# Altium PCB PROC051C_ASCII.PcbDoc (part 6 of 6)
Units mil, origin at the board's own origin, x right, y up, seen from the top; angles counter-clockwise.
Board outline 3304.03 x 2647.77 mil, 6 copper layers (TOP, L2, L3, L4, L5, BOTTOM), stack 55.54 mil thick; 370 components, 273 nets, 1273 pads, 1381 vias.
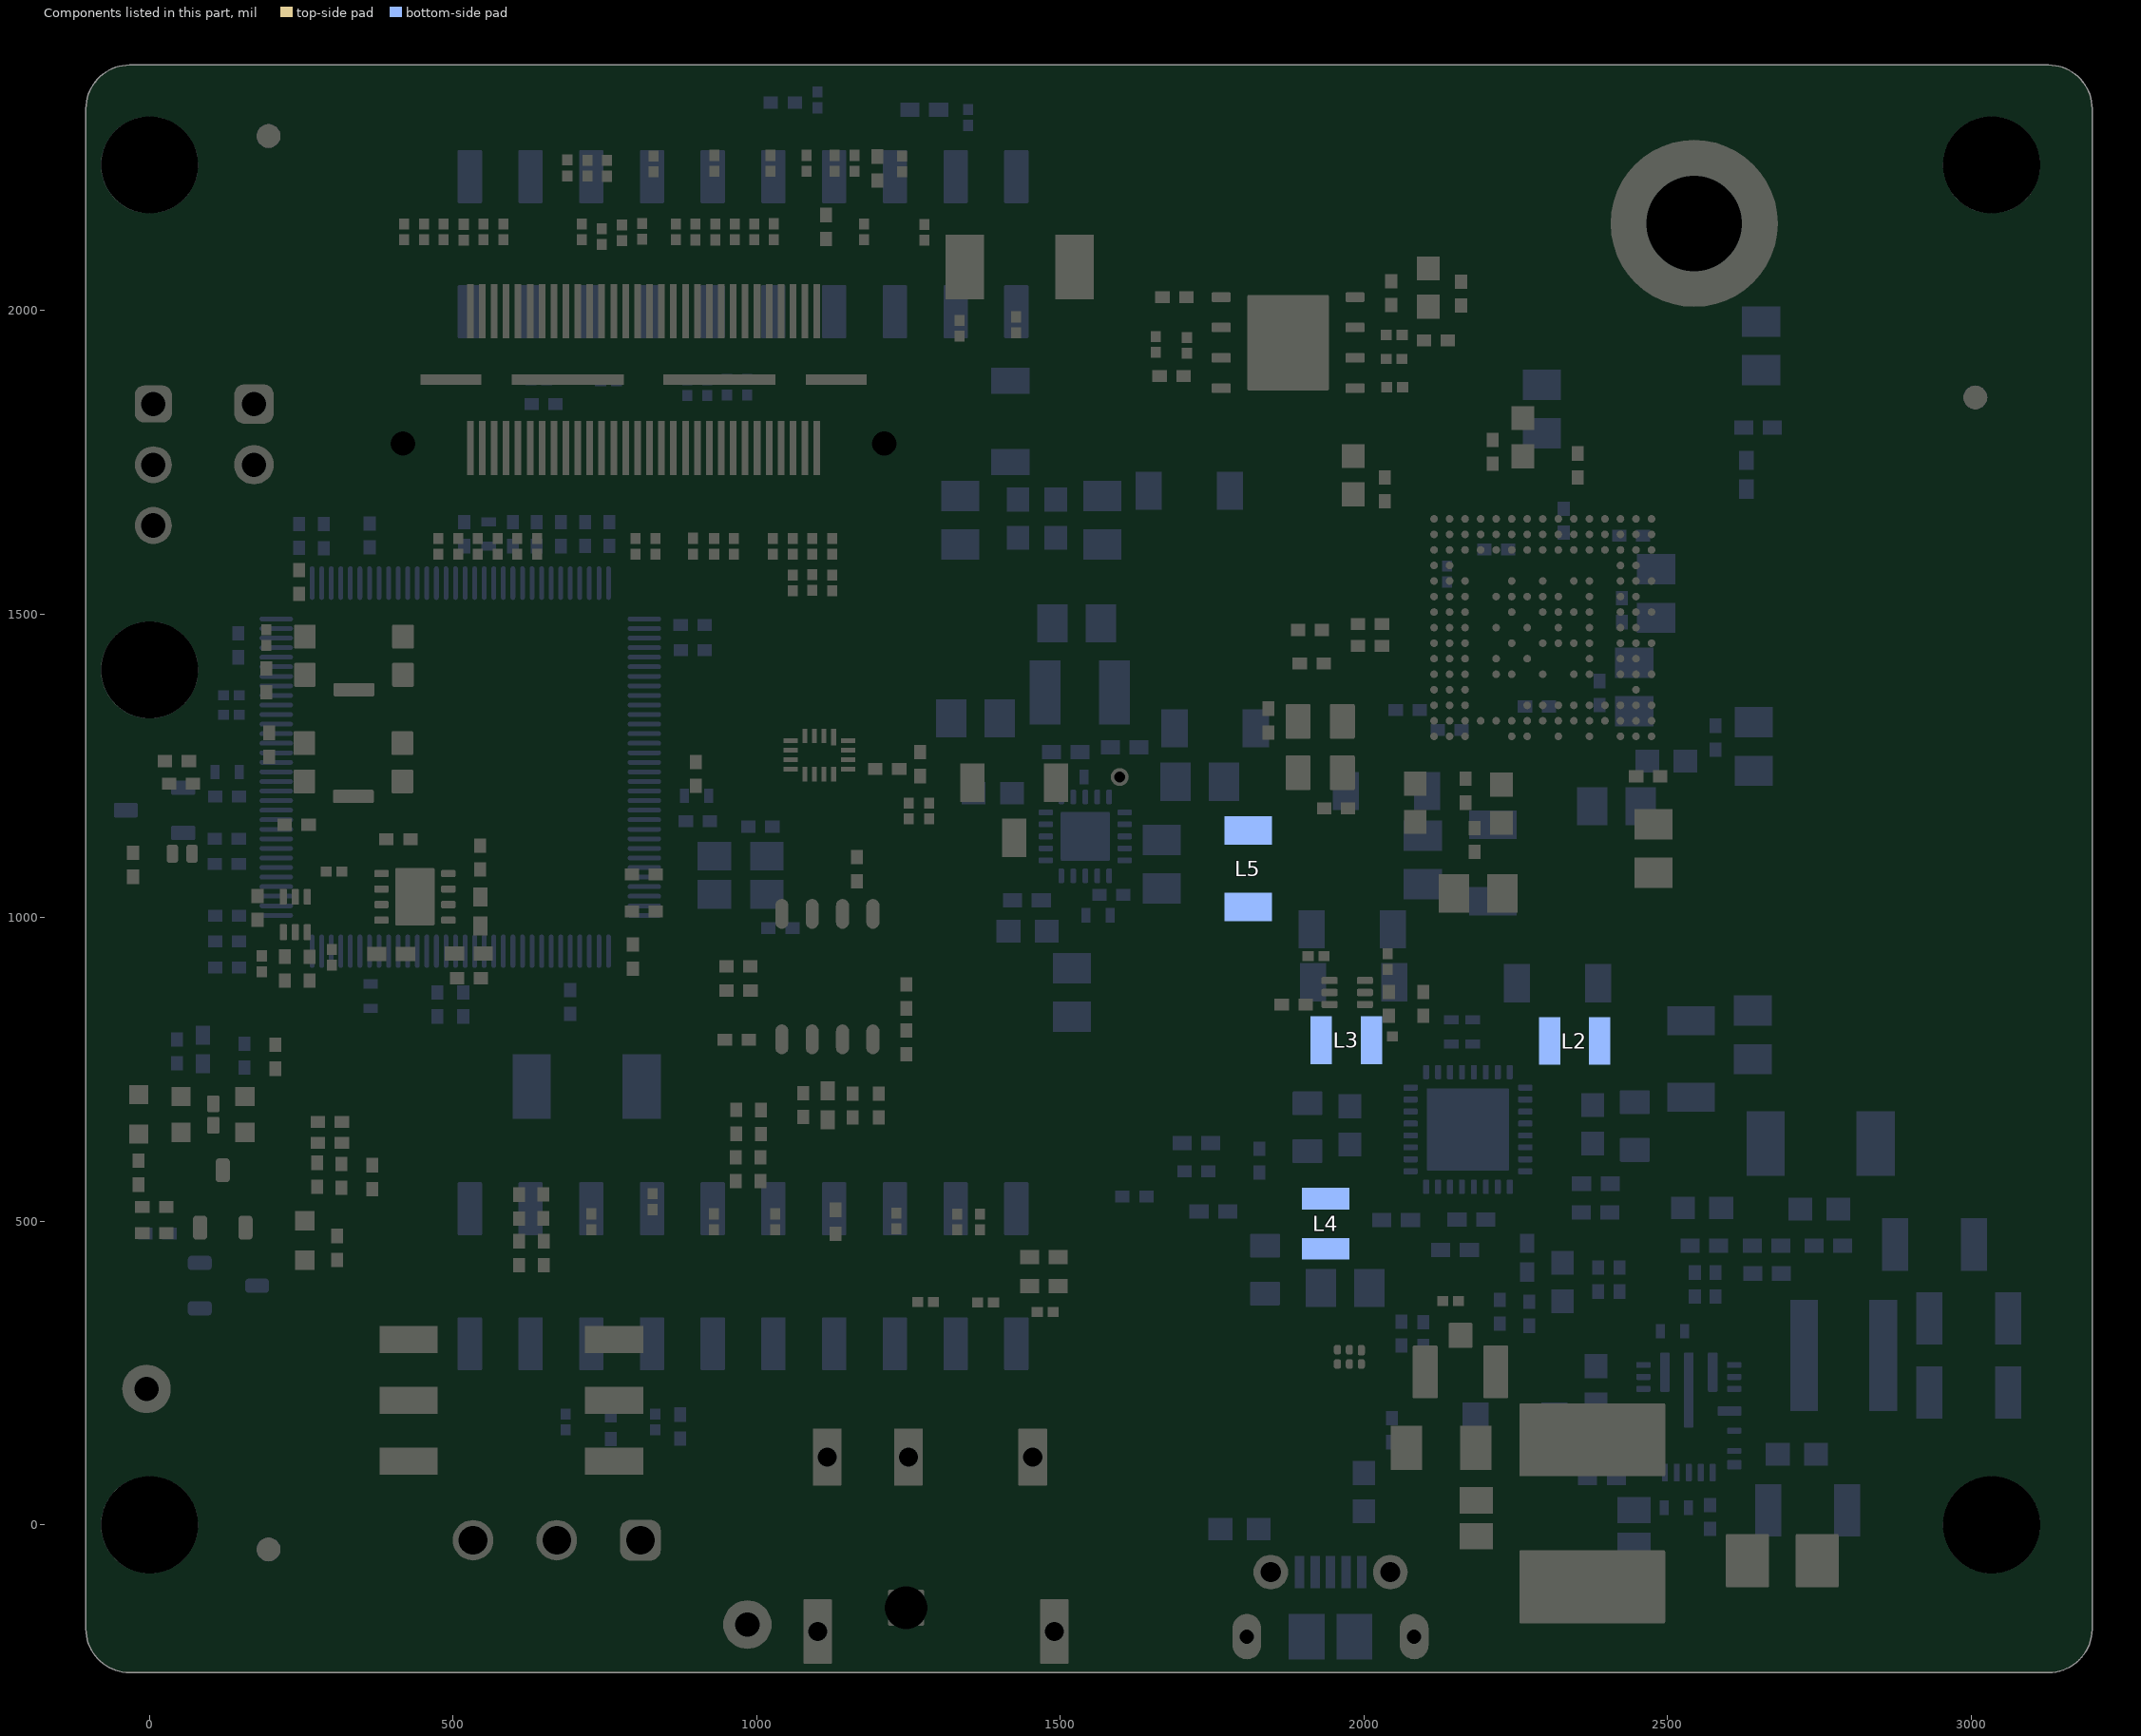
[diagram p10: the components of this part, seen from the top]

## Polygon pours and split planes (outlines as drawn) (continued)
no net on M5 Assembly Top (solid): 3048.2,1870.7 ccw(c3006.2,1870.7) 3006.2,1912.7 ccw(c3006.2,1870.7) 2964.2,1870.7 ccw(c3006.2,1870.7) 3006.2,1828.7 ccw(c3006.2,1870.7) 3048.2,1870.7
no net on M5 Assembly Top (solid): 238,-40.5 ccw(c196,-40.5) 196,1.5 ccw(c196,-40.5) 154,-40.5 ccw(c196,-40.5) 196,-82.5 ccw(c196,-40.5) 238,-40.5
GND on L5 "L5_GND_P1103" (solid, remove dead copper, pour order 1103): 3156.74,-243.26 -87.75,-243.25 -116,-214.99 -116,2367 -75,2408 3157,2408 3199.26,2365.74 3199.26,-200.74

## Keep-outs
TOP:
  circle w10: c3033.56,2240 r92.09
  circle w10: c3033.56,0 r92.09
L2:
  circle w10: c1209.9,1781.14 r44.95
  circle w10: c417.38,1781.14 r44.95
  circle w10: c3033.56,0 r92.09
  circle w10: c3033.56,2240 r92.09
L3:
  circle w10: c3033.56,2240 r92.09
  circle w10: c3033.56,0 r92.09
L4:
  circle w10: c1209.9,1781.14 r44.95
  circle w10: c3033.56,0 r92.09
  circle w10: c3033.56,2240 r92.09
L5:
  circle w10: c1209.9,1781.14 r44.95
  circle w10: c417.38,1781.14 r44.95
  circle w10: c3033.56,2240 r92.09
  circle w10: c3033.56,0 r92.09
BOTTOM:
  circle w10: c3033.56,2240 r92.09
  circle w10: c3033.56,0 r92.09
Keep-Out Layer:
  lines w4: -102.75,-171.24 ccw(c-32.75,-171.24) -32.75,-241.24 3127.25,-241.24 ccw(c3127.25,-171.24) 3197.25,-171.24 3197.25,2332.5 ccw(c3127.25,2332.5) 3127.25,2402.5 -32.75,2402.5 ccw(c-32.75,2332.5) -102.75,2332.5 -102.75,-171.24
  text ".Layer_Name" at 269,-1200.49 h60

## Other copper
TOP:
  text ".Layer_Name" at 269,-1200.49 h60
L2:
  text ".Layer_Name" at 265.96,-1198.29 h60
L3:
  text ".Layer_Name" at 266.3,-1199.15 h60
L4:
  text ".Layer_Name" at 270.35,-1203.19 h60
L5:
  text ".Layer_Name" at 265.96,-1201.5 h60
BOTTOM:
  text ".Layer_Name" at 269,-1200.49 h60

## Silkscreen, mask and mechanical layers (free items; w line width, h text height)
Top Overlay:
  lines w6: 1944.01,252.57 1944.01,304.68 2000.32,304.68 2008.7,296.3 2008.7,252.57 1944.01,252.57
  lines w10: 56,1744 73.53,1726.47 90.78,1709.22 90.78,1631.82 84.96,1637.64 97.42,1637.64 91.6,1631.82 ; 117,629 118,629 133,614 145,614 ; 259.69,1058.63 ccw(c266.87,1055.3) 259.69,1058.63 ; 359.73,1070.26 ccw(c366.91,1066.94) 359.73,1070.26 ; 827.2,103.68 ccw(c834.38,100.36) 827.2,103.68 ; 1098.62,2058.28 ccw(c1105.8,2054.96) 1098.62,2058.28 ; 1126.81,1323.46 ccw(c1133.99,1320.13) 1126.81,1323.46 ; 1191.31,1043.36 ccw(c1198.49,1040.04) 1191.31,1043.36 ; 1731,2042.5 ccw(c1738.18,2039.17) 1731,2042.5
  lines w25: 1280,1667.5 1280,2079.5 ; 1683.5,655.5 1986,655.5
  lines w30: 1276,742 1276,655.5 1357.1,655.5 ; 1276,932 1276,1112 ; 1598,2095.5 2044,2095.5 ; 2166,2095.5 2372,2095.5 ; 2668,1805.5 2668,2019.5
  text "1" at 1168,2055 h30 r90
  text "59" at 471,2041 h30 r90
  text "HD_CONN" at 302,1910 h30 r90
  text "VPP_1P7" at 278,1714 h30 r90
  text "2" at 1167,1706 h30 r90
  text "60" at 476,1681 h30 r90
  text "GND" at 106,1531 h30 r90
  text "1843-EVM" at 1345,1523 h30
  text "PROC051" at 1291,1458 h30
  text "REV C" at 1502,1456 h30
  text "GPIO1" at 548,1388 h30 r90
  text "SPI" at 1510,1277 h30 r90
  text "CAN" at 1368,1275 h30 r90
  text "NRST" at 548,1203 h30 r90
  text "GPIO_2" at -2,755.84 h30 r90
  text "WRM_RST" at 66,751 h30 r90
  text "NERR" at 171,749 h30 r90
  text "PWR" at 121,748 h30 r90
  text "NRST" at 256.76,548 h30 r90
  text "ON" at 509,403 h30 r90
  text "OFF" at 709,402 h30 r90
  text "SOP0" at 243,290 h30
  text "SOP1" at 249,190 h30
  text "5V_IN" at 1130,173 h30 r90
  text "SOP2" at 242,93 h30
  text "USB" at 1958,-107 h30 r90
  text "GND" at 702,-148 h30 r90
  text "CAN_L" at 541,-209 h30 r90
  text "CAN_H" at 819,-209 h30 r90
  text ".Layer_Name" at 269,-1200.49 h60
Bottom Overlay:
  drawing of 5487 lines, arcs and shapes, not listed
  text "GND" at 545,2389 h35 r90
  text "20" at 1517,2269 h30 r90
  text "2" at 465,2248 h30 r90
  text "19" at 1522,2037 h30 r90
  text "1" at 466,1986 h30 r90
  text "P1" at 14,1946 h30 r90
  text "P7" at 262,1899 h30 r90
  text "WD_ENABLE" at 1778,670 h30
  text "GND" at 640,644 h25 r90
  text "20" at 1522,552 h30 r90
  text "2" at 454,502 h30 r90
  text "WD_DISABLE" at 1793,448 h30
  text "1" at 457,339 h30 r90
  text "19" at 1520,330 h30 r90
  text "GND" at 654,207 h30 r90
  text "5V_IN" at 1551,194 h30 r90
  text "CAN_H" at 931,98 h30 r90
  text "CAN_L" at 439,94 h30 r90
  text ".Layer_Name" at 269,-1200.49 h60
Top Paste:
  text ".Layer_Name" at 269,-1200.49 h60
Bottom Paste:
  text ".Layer_Name" at 269,-1200.49 h60
Top Solder:
  text ".Layer_Name" at 269,-1200.49 h60
  text ".Layer_Name" at 269,-1200.49 h60
Bottom Solder:
  text ".Layer_Name" at 269,-1200.49 h60
Drill Guide:
  text ".Layer_Name" at 269,-1200.49 h60
M1 Board Outline:
  lines w4: -102.75,-171.24 ccw(c-32.75,-171.24) -32.75,-241.24 3127.25,-241.24 ccw(c3127.25,-171.24) 3197.25,-171.24 ; -102.75,-171 -102.75,2331.5 ; -102.75,2332.5 cw(c-32.75,2332.5) -32.75,2402.5 3127.25,2402.5 cw(c3127.25,2332.5) 3197.25,2332.5 3197.25,-172
  text ".Layer_Name" at 270.78,-1200.89 h60
M2 Board Dimensions:
  rectangle: -183,-742 192,-617
  rectangle: -308,-617 -183,-492
  lines w7: -308,-617 692,-617 ; -183,-742 -183,-492 ; -58,-742 -58,-492 ; 192,-742 192,-492 ; 442,-742 442,-492 ; -308,-742 -308,-492 692,-492 692,-742 -308,-742
  text ".Layer_Name" at 268.79,-1200.89 h60
M3 3D STEP Top:
  text ".Layer_Name" at 269,-1200.49 h60
M4 3D STEP Bottom:
  lines w6: 711,2169 705,2169 ; 1282,2245 1333,2245 1374,2204 1731,2204 1763,2236 1763,2317 1709,2371 1327,2371 1282,2326 1282,2227 1246,2191 1062,2191 1048,2177 1048,2169 ; 705,2169 1048,2169 ; 705,2169 693,2157 693,2093 703,2083 1043,2083 1054,2094 1054,2163 1048,2169
  text ".Layer_Name" at 269,-1200.49 h60
M5 Assembly Top:
  lines w10: -600,-1272.17 6000,-1272.17 ; -600,-1068.83 6002,-1068.83 ; -600,-865.5 -600,-1475.5 3405,-1475.5 6002,-1475.5 6002,-865.5 -599.5,-865.5 -599.5,-1475.5 976,-1475.5 ; 1865,-1475.5 1865,-865.5 ; 3132,-1068.83 3132,-865.5 ; 3972,-1068.83 3972,-865.5 ; 4594,-1482 4594,-1279.17
  text "COMPONENTS MARKED 'DNP' SHOULD NOT BE POPULATED." at 845.5,-660.5 h60
  text "ASSEMBLY VARIANT:" at 845,-776 h60
  text ".VariantName" at 1881,-776 h60
  text "PCB VIEWED FROM TOP SIDE" at -536.5,-997.67 h60
  text "BOARD #:" at 1940,-997.67 h60
  text ".PRJ_Number" at 2485.5,-997.67 h60
  text "REV:" at 3330,-997.67 h60
  text ".PCB_Rev" at 3621.5,-997.67 h60
  text "SVN REV:" at 4168,-997.67 h60
  text ".VersionControl_RevNumber" at 4674,-997.67 h60
  text ".Layer_Name" at 269,-1200.49 h60
  text "TID #:" at 1940,-1201 h60
  text ".TID" at 2485.5,-1201 h60
  text "LAYER NAME =" at -525.56,-1204.81 h60
  text "PLOT NAME =" at -536.5,-1406.34 h60
  text ".plot_File_Name" at 269,-1406.34 h60
  text "GENERATED    :" at 1942,-1406.34 h60
  text ".Print_Date" at 2811.5,-1406.34 h60
  text ".Print_Time" at 3540.5,-1406.34 h60
  text "TEXAS INSTRUMENTS" at 4805,-1406.34 h60
M6 Assembly Bottom:
  lines w10: -600.5,-1069.33 6001.5,-1069.33 ; -598.5,-1272.67 6001.5,-1272.67 ; 807.5,-1482.5 807.5,-1279.67 ; 1429.5,-1069.33 1429.5,-866 ; 2269.5,-1069.33 2269.5,-866 ; 3536.5,-1476 3536.5,-866 ; 4425.5,-1476 6001,-1476 6001,-866 -600.5,-866 -600.5,-1476 1996.5,-1476 6001.5,-1476 6001.5,-866
  text "COMPONENTS MARKED 'DNP' SHOULD NOT BE POPULATED." at 5794,-660 h60
  text ".VariantName" at 4750,-776 h60
  text "ASSEMBLY VARIANT:" at 5789,-776 h60
  text ".VersionControl_RevNumber" at 727.5,-998.17 h60
  text "SVN REV:" at 1233.5,-998.17 h60
  text ".PCB_Rev" at 1780,-998.17 h60
  text "REV:" at 2071.5,-998.17 h60
  text ".PRJ_Number" at 2916,-998.17 h60
  text "BOARD #:" at 3461.5,-998.17 h60
  text "PCB VIEWED FROM BOTTOM SIDE" at 5938,-998.17 h60
  text ".TID" at 2916,-1201.5 h60
  text "TID #:" at 3461.5,-1201.5 h60
  text "LAYER NAME =" at 5938.09,-1203.59 h60
  text ".Layer_Name" at 5191.24,-1206.1 h60
  text "TEXAS INSTRUMENTS" at 596.5,-1406.84 h60
  text ".Print_Time" at 1861,-1406.84 h60
  text ".Print_Date" at 2590,-1406.84 h60
  text "GENERATED    :" at 3459.5,-1406.84 h60
  text ".plot_File_Name" at 5132.5,-1406.84 h60
  text "PLOT NAME =" at 5938,-1406.84 h60
M9 Title Sheet:
  lines w10: -799.5,699.5 -599.5,699.5 ; -799.5,3074.5 -599.5,3074.5 ; -799.5,5449.5 -599.5,5449.5 ; 1700.5,-1675.5 1700.5,-1475.5 ; 1700.5,7624.5 1700.5,7824.5 ; 4200.5,-1675.5 4200.5,-1475.5 ; 4200.5,7624.5 4200.5,7824.5 ; 6013,-1475.5 6013,-865.5 10995.5,-865.5 ; 6700.5,-1675.5 6700.5,-1475.5 ; 6700.5,7624.5 6700.5,7824.5 ; 9200.5,-1675.5 9200.5,-1475.5 ; 9200.5,7624.5 9200.5,7824.5 ; 10995.5,-1475.5 10995.5,-865.5 ; 10995.5,-1165.5 13995.5,-1165.5 ; 10995.5,-565.5 13995.5,-565.5 ; 10996.5,28.5 13996.5,28.5 ; 11700.5,-1675.5 11700.5,-1475.5 ; 11700.5,7624.5 11700.5,7824.5 ; 12500.5,-1465.5 12500.5,-865.5 ; 13995.5,-865.5 10995.5,-865.5 ; 13995.5,-265.5 10995.5,-265.5 ; 14000.5,-275.5 14000.5,-1475.5 ; 14000.5,529 10996.5,529 10995.5,529 10995.5,28.5 10995.5,-265.5 ; 14000.5,699.5 14200.5,699.5 ; 14000.5,3074.5 14200.5,3074.5 ; 14000.5,5449.5 14200.5,5449.5 ; 10995.5,-865.5 10995.5,-265.5 ; 14000.5,-1475.5 -599.5,-1475.5 -599.5,7624.5 14000.5,7624.5 14000.5,-1475.5 ; -799.5,-1675.5 14200.5,-1675.5 14200.5,7824.5 -799.5,7824.5 -799.5,-1675.5
  text "1" at 431.84,7694.5 h70
  text "2" at 2927.5,7694.5 h70
  text "3" at 5416.84,7694.5 h70
  text "4" at 7923.51,7694.5 h70
  text "5" at 10422.5,7694.5 h70
  text "6" at 12927.5,7694.5 h70
  text "A" at -724.5,6551.5 h70
  text "A" at 14075.5,6551.5 h70
  text "B" at -724.5,4171.5 h70
  text "B" at 14075.5,4171.5 h70
  text "C" at -724.5,1796.5 h70
  text "C" at 14075.5,1796.5 h70
  text "PROJECT TITLE:" at 11035.5,-64.5 h45
  text ".PRJ_Title" at 11085.5,-197.83 h70
  text "DESIGNED FOR:" at 11035.5,-365.5 h45
  text ".PRJ_Customer" at 11085.5,-505.5 h70
  text "D" at -724.5,-573.5 h70
  text "D" at 14075.5,-573.5 h70
  text "FILE NAME:" at 11035.5,-665.5 h45
  text ".PCB_File_Name_No_Path" at 11085.5,-785.5 h70
  text "Texas Instruments (TI) and/or its licensors do not warrant the accuracy or completeness of this specification" at 6066,-947.34 h45
  text "ENGINEER:" at 11035.5,-955.5 h45
  text "LAYOUT BY:" at 12540.5,-955.5 h45
  text "or any information contained therein. TI and/or its licensors do not warrant that this design will meet" at 6021.01,-1060 h45
  text ".PRJ_Engineer" at 11085.5,-1110.49 h70
  text ".PCB_Layout" at 12591,-1110.49 h70
  text "the specifications, will be suitable for your application or fit for any particular purpose, or will operate in" at 6021.01,-1172.67 h45
  text ".Layer_Name" at 270,-1201.17 h60
  text "ALTIUM DESIGNER VERSION:" at 12540.5,-1265.5 h45
  text "an implementation. TI and/or its licensors do not warrant that the design is production worthy. You should" at 6021.01,-1285.33 h45
  text "completely validate and test your design implementation to confirm the system functionality for your application." at 6066,-1398 h45
  text ".print_Scale" at 11085.5,-1398.83 h70
  text ".Application_BuildNumber" at 12591,-1398.83 h70
  text "1" at 431.84,-1605.5 h70
  text "2" at 2927.5,-1605.5 h70
  text "3" at 5416.84,-1605.5 h70
  text "4" at 7923.51,-1605.5 h70
  text "5" at 10422.5,-1605.5 h70
  text "6" at 12927.5,-1605.5 h70
M10 Fab Notes:
  drawing of 189 lines, arcs and shapes, not listed
  text "DESIGN INFORMATION" at 12074.02,6014.17 h60
  text "MIN. TRACK WIDTH:" at 11429.46,5882.05 h60
  text "MIL" at 12680.46,5882.05 h60
  text "4" at 12497.65,5875.46 h60
  text "MIN. CLEARANCE:" at 11429.46,5757.92 h60
  text "MIL" at 12680.46,5757.92 h60
  text "3" at 12500.45,5756.91 h60
  text "MIN. VIA PAD SIZE:" at 11429.46,5633.8 h60
  text "12.6" at 12418.45,5630.91 h60
  text "MIL" at 12711.42,5628.39 h60
  text "0.05mm (2MIL)" at 12124.46,5503.9 h60
  text "MINIMUM ANNULAR RING" at 11100.23,5495.67 h60
  text "EXTERNAL" at 12832.46,5495.67 h60
  text "PER" at 11300.23,5385.55 h60
  text "IPC-D-275 CLASS 2 LEVEL C" at 11520.23,5385.54 h60
  text "MIL, HOLES" at 13008.46,5285.07 h60
  text "+/-" at 12616,5276.48 h60
  text "+/-" at 13470,5276.48 h60
  text "REGISTRATION TOLERANCES:" at 11100.23,5275.42 h60
  text "METAL" at 12300,5275.42 h60
  text "2" at 12876.2,5275.42 h60
  text "3" at 13709.2,5275.42 h60
  text "MIL" at 13825.46,5275.42 h60
  text "HOLE SIZE TOLERANCE (UNLESS OTHERWISE SPECIFIED):" at 11100.23,5177.1 h60
  text "+/-" at 13470,5174.23 h60
  text "3" at 13709.2,5173.17 h60
  text "MIL" at 13825.46,5173.17 h60
  text "MATERIAL:" at 11025.46,5035.52 h60
  text "FR-4 High Tg" at 12011.9,4907 h60
  text "X" at 12756.42,4898.55 h60
  text "FR-408" at 11446.46,4894.49 h60
  text "OTHER" at 12934.46,4894.49 h60
  text "REFER STACKUP" at 13277.53,4884.65 h60
  text "56.214 MIL(1.42mm) +/-10%" at 11766.56,4751.46 h55
  text "X" at 12936.04,4749.1 h60
  text "57.14 MIL +/-10%" at 13329.52,4748.23 h50
  text "THICKNESS:" at 11100.23,4743.24 h60
  text "OTHER" at 13051.46,4743.24 h60
  text "TOLERANCE:" at 11100.23,4604.92 h60
  text "X" at 11948.46,4604.92 h60
  text "ANSI IPC-6012 TYPE 3 CLASS 2" at 12126.48,4604.92 h60
  text "OTHER +/-" at 12126.46,4460.73 h60
  text "BOW & TWIST:" at 11100.23,4315.54 h60
  text "X" at 11948.46,4315.54 h60
  text "ANSI IPC-6012 TYPE 3 CLASS 2" at 12126.48,4315.54 h60
  text "OTHER +/-" at 12126.46,4168.85 h60
  text "DRILLING:" at 11025.46,4038.23 h60
  text "NC_DRILL FILES" at 12786.46,3933.04 h60
  text "REFERENCE:" at 11100.23,3929.1 h60
  text "X" at 11757.46,3929.01 h60
  text "AS SHOWN" at 11935.46,3929.1 h60
  text "X" at 12658.46,3929.1 h60
  text "OTHER" at 13084.46,3786.85 h60
  text "PTH COPPER THICKNESS:" at 11099.91,3783.32 h60
  text "X" at 12239.14,3783.32 h60
  text "20-30 um" at 12367.14,3783.32 h60
  text "BOARD FINISH:" at 11025.46,3635.73 h60
  text "SILKSCREEN:" at 11180.68,3525.6 h60
  text "X" at 12138.46,3525.6 h60
  text "TOP" at 12255.46,3525.6 h60
  text "X" at 12648.46,3525.6 h60
  text "BOTTOM" at 12766.46,3525.6 h60
  text "SILKSCREEN COLOR:" at 11180.68,3370.41 h60
  text "X" at 12137.46,3370.41 h60
  text "WHITE" at 12255.46,3370.41 h60
  text "OTHER" at 12766.46,3370.41 h60
  text "X" at 12850.6,3228.22 h60
  text "GREEN" at 12386.46,3226.96 h60
  text "OTHER" at 13004.46,3226.96 h60
  text "RED" at 13528.15,3225.88 h60
  text "SOLDER RESIST COLOR:" at 11180.68,3220.1 h60
  text "X" at 12268.46,3072.71 h60
  text "MATTE" at 12386.46,3072.71 h60
  text "SEMI-GLOSS" at 13004,3072.07 h60
  text "IMMERSION GOLD (ENIG)" at 12086.46,2899.94 h60
  text "ENEPIG" at 13424,2892.72 h60
  text "SURFACE FINISH:" at 11025.46,2891.72 h60
  text "IMMERSION SILVER" at 13125.67,2754.86 h60
  text "IMM. TIN/SILVER OR EQUIV" at 11355,2754.4 h60
  text "OTHER" at 12786.46,2750.47 h60
  text "X" at 12603.67,2746.86 h60
  text "NOTES: UNLESS OTHERWISE SPECIFIED." at 4751.98,2687.86 h60
  text "ARRAY/PANEL:" at 11025.46,2595.09 h60
  text "X" at 11906.1,2586.66 h60
  text "CUT AND TRIM PER M1 BOARD OUTLINE" at 12086.46,2586.87 h60
  text "N.C. ROUTE" at 12086.46,2450.9 h60
  text "V. SCORE" at 12952.46,2450.9 h60
  text "1. FOR BOARD THICKNESS AND IMPEDANCE DETAILS REFER STACKUP DOCUMENT." at 4751.98,2425.86 h60
  text "CERTIFICATION:" at 11025.46,2321.77 h60
  text "MATERIALS AND WORKMANSHIP FOR ALL PCBS" at 11750.46,2321.77 h60
  text "2. ALL VIAS ON PAD INCLUDING BGA AREA SHOULD BE FILLED WITH NON CONDUCTIVE EPOXY AND SURFACE SHOULD BE FLAT" at 4741.5,2320.42 h60
  text "TO MEET OR EXCEED THE REQUIREMENTS OF:" at 11750.46,2227.71 h60
  text "THERE ARE MANY VIAS ON THE PCB WHICH ARE EITHER ON THE PADS OR CLOSE TO PADS" at 4860.28,2213.13 h60
  text "THESE NEED TO BE FILLED WITH A NON-CONDUCTIVE EPOXY TO ENSURE FLAT SURFACE." at 4860.28,2112.39 h60
  text "X" at 11387.97,2099.08 h60
  text "ANSI IPC-A-600F CLASS ->" at 11515.96,2099.08 h60
  text "X" at 13163.97,2099.08 h60
  text "2" at 13273.96,2099.08 h60
  text "1" at 12958.96,2097.58 h60
  text "3" at 13627.96,2097.58 h60
  text "BGA AREA VIAS SHOULD BE CAPPED WITH COPPER PLATING TO ENSURE FLAT SURFACE" at 4865.78,2010.86 h60
  text "RoHS" at 12327.96,1951.39 h60
  text "OTHER" at 12972.36,1951.39 h60
  text "PER ORDER" at 13369.42,1951.39 h60
  text "FLATNESS TOLERANCE FOR VIA ON PADS: +0.000 /- 0.001 INCHES ON BOTH SIDES." at 4865.78,1902.77 h60
  text "ALL BOARDS MUST MEET OR EXCEED UL94-V0 REQUIREMENTS." at 11053,1797.57 h60
  text "3. SOLDER MASK OPENING IS KEPT SAME SIZE AS PAD (1:1)" at 4739.9,1789.33 h60
  text "THE MANUFACTURER IS REQUESTED TO RESIZE IT AS PER THEIR SOLDERMASK TOLERANCE EXCEPT NPTH DRILL AND FIDUCIALS." at 4904.94,1687.68 h60
  text "PCB MUST BEAR THE UL94V-0 UL REGISTERED MATERIAL ID NUMBER" at 11053,1681.5 h60
  text "4. VENDOR SHOULD FOLLOW ROHS COMPLIANT PROCESS AND Pb FREE FOR MANUFACTURING" at 4747.64,1564.84 h60
  text "ADDITIONAL REQUIREMENTS:" at 11025.46,1512.08 h60
  text "5. MANUFACTURER'S IDENTIFICATION,DATECODE LETTER SHALL BE SILKSCREENED ON SOLDER SIDE" at 4748.29,1437.55 h60
  text "MICROSECTION:" at 11100.23,1404.95 h60
  text "YES" at 12005.96,1404.95 h60
  text "OF THE BOARD." at 4918.29,1324.55 h60
  text "REQUIRED" at 12867.46,1260.62 h60
  text "BARE BOARD ELEC. TEST:" at 11100.23,1257.76 h60
  text "NONE" at 12405.96,1257.76 h60
  text "X" at 12749.46,1257.76 h60
  text "PER ORDER" at 13459.46,1257.76 h60
  text "6. TRACE WIDTH SHOULD BE ACCURATELY ETCHED. MAX TOLERANCE +/- 1 MIL" at 4748.29,1210.55 h60
  text "7. BOARD DIMENSIONS ARE IN (INCHES)." at 4748.29,1071.55 h60
  text "XX MIL VIAS REQUIRE NON-CONDUCTIVE FILL AND PLANARIZE" at 11268.38,1052.82 h59
  text "XX MIL VIAS REQUIRE CONDUCTIVE FILL AND PLANARIZE" at 11276.38,948.84 h60
  text "8. BOW AND TWIST SHALL NOT EXCEED 0.7% OF LONGEST SIDE" at 4748.29,929.55 h60
  text "9. LAYER TO LAYER REGISTRATION SHALL BE WITHIN +/-2 MIL" at 4748.98,813.84 h60
  text "OUTER XX MIL TRACES REQUIRE 50 OHM SINGLE-ENDED IMPEDANCE" at 11275.39,785.46 h55
  text "10. FOR ANTENNA ETCHING TOLERANCE REFER \"ANTENNA ETCHING REQUIREMENTS\" DOCUMENT." at 4705.37,694.61 h60
  text "LAYER 2 & 3 (INNER LAYERS) XX MIL WIDE, XX MIL SPACE / TRACES REQUIRE 100 OHM DIFFERENTIAL IMPEDANCE" at 11267.39,549.74 h60
  text ".Layer_Name" at 270.6,-1200.89 h60
M11 Gerber Information:
  lines w10: -600,-1272.17 6000,-1272.17 ; -600,-1068.83 6002,-1068.83 ; -600,-865.5 -600,-1475.5 3405,-1475.5 6002,-1475.5 6002,-865.5 -599.5,-865.5 -599.5,-1475.5 976,-1475.5 ; 1865,-1475.5 1865,-865.5 ; 3132,-1068.83 3132,-865.5 ; 3972,-1068.83 3972,-865.5 ; 4594,-1482 4594,-1279.17
  text "ALL ARTWORK VIEWED FROM TOP SIDE" at -536.5,-997.67 h60
  text "BOARD #:" at 1940,-997.67 h60
  text ".PRJ_Number" at 2485.5,-997.67 h60
  text "REV:" at 3330,-997.67 h60
  text ".PCB_Rev" at 3621.5,-997.67 h60
  text "SVN REV:" at 4168,-997.67 h60
  text ".VersionControl_RevNumber" at 4674,-997.67 h60
  text "LAYER NAME =" at -536.5,-1200.49 h60
  text "TID #:" at 1940,-1201 h60
  text ".TID" at 2485.5,-1201 h60
  text "PLOT NAME =" at -536.5,-1406.34 h60
  text ".plot_File_Name" at 269,-1406.34 h60
  text "GENERATED    :" at 1942,-1406.34 h60
  text ".Print_Date" at 2811.5,-1406.34 h60
  text ".Print_Time" at 3540.5,-1406.34 h60
  text "TEXAS INSTRUMENTS" at 4805,-1406.34 h60
M12 Stackup:
  drawing of 417 lines, arcs and shapes, not listed
  text "LAYER STACKUP :" at 5183.41,7377.07 h60
  text "Layer" at 5204.39,7196.49 h60
  text "Name" at 5614.31,7196.49 h60
  text "Material" at 6544.05,7196.49 h60
  text "Thickness" at 7733.71,7196.49 h60
  text "Constant" at 8383.55,7196.49 h60
  text "Board Layer Stack" at 8953.41,7196.49 h60
  text "1" at 5204.39,7076.49 h60
  text "Top Overlay" at 5614.31,7076.49 h60
  text "2" at 5204.39,6956.49 h60
  text "Top Solder" at 5614.31,6956.49 h60
  text "Solder Resist" at 6544.05,6956.49 h60
  text "0.80mil" at 7733.71,6956.49 h60
  text "3.5" at 8383.55,6956.49 h60
  text "3" at 5204.39,6836.49 h60
  text "TOP" at 5614.31,6836.49 h60
  text "Copper" at 6544.05,6836.49 h60
  text "1.60mil" at 7733.71,6836.49 h60
  text "4" at 5204.39,6716.49 h60
  text "Dielectric1" at 5614.31,6716.49 h60
  text "Rogers 4835" at 6544.05,6716.49 h60
  text "4.00mil" at 7733.71,6716.49 h60
  text "3.66" at 8383.55,6716.49 h60
  text "L1-L2" at 4858.49,6644.53 h60 r90
  text "5" at 5204.39,6596.49 h60
  text "L2" at 5614.31,6596.49 h60
  text "Copper" at 6544.05,6596.49 h60
  text "1.20mil" at 7733.71,6596.49 h60
  text "6" at 5204.39,6476.49 h60
  text "Dielectric2" at 5614.31,6476.49 h60
  text "370HR Prepreg 1080" at 6544.05,6476.49 h60
  text "5.70mil" at 7733.71,6476.49 h60
  text "3.9" at 8383.55,6476.49 h60
  text "7" at 5204.39,6356.49 h60
  text "L3" at 5614.31,6356.49 h60
  text "Copper" at 6544.05,6356.49 h60
  text "1.20mil" at 7733.71,6356.49 h60
  text "8" at 5204.39,6236.49 h60
  text "Dielectric3" at 5614.31,6236.49 h60
  text "370HR Prepreg 1080" at 6544.05,6236.49 h60
  text "28.00mil" at 7733.71,6236.49 h60
  text "4.36" at 8383.55,6236.49 h60
  text "L1-L6" at 4676.89,6155.29 h60 r90
  text "9" at 5204.39,6116.49 h60
  text "L4" at 5614.31,6116.49 h60
  text "Copper" at 6544.05,6116.49 h60
  text "1.20mil" at 7733.71,6116.49 h60
  text "10" at 5204.39,5996.49 h60
  text "Dielectric4" at 5614.31,5996.49 h60
  text "370HR Prepreg 1080" at 6544.05,5996.49 h60
  text "5.84mil" at 7733.71,5996.49 h60
  text "3.9" at 8383.55,5996.49 h60
  text "11" at 5204.39,5876.49 h60
  text "L5" at 5614.31,5876.49 h60
  text "Copper" at 6544.05,5876.49 h60
  text "1.20mil" at 7733.71,5876.49 h60
  text "12" at 5204.39,5756.49 h60
  text "Dielectric5" at 5614.31,5756.49 h60
  text "370HR Prepreg 1080" at 6544.05,5756.49 h60
  text "4.00mil" at 7733.71,5756.49 h60
  text "4.26" at 8383.55,5756.49 h60
  text "13" at 5204.39,5636.49 h60
  text "BOTTOM" at 5614.31,5636.49 h60
  text "Copper" at 6544.05,5636.49 h60
  text "1.60mil" at 7733.71,5636.49 h60
  text "14" at 5204.39,5516.49 h60
  text "Bottom Solder" at 5614.31,5516.49 h60
  text "Solder Resist" at 6544.05,5516.49 h60
  text "0.80mil" at 7733.71,5516.49 h60
  text "3.5" at 8383.55,5516.49 h60
  text "15" at 5204.39,5396.49 h60
  text "Bottom Overlay" at 5614.31,5396.49 h60
  text "IMPEDANCE TABLE :" at 5347.56,5063.25 h70
  text "LAYER NO" at 5399.74,4721.7 h70
  text "CONDUCTOR WIDTH" at 6045.26,4721.7 h70
  text "IMPEDANCE +/-10%" at 8245.23,4721.57 h70
  text "REFERENCE GND" at 9426.27,4721.57 h70
  text "DIFF. / PAIR / SPACING" at 7107.21,4661.55 h70
  text "CPWG / SPACING" at 7645.56,4655.96 h70
  text "5.2mil" at 6284.33,4501.43 h70
  text "L2-GND" at 9641.61,4499.79 h70
  text "5mil" at 7214.22,4496.4 h70
  text "N/A" at 7749.12,4496.27 h70
  text "100ohm" at 8515.32,4496.35 h70
  text "1 (TOP)" at 5469.46,4493.72 h70
  text ".Layer_Name" at 268.79,-1200.89 h60
M13 Component Bodies Top:
  text ".Layer_Name" at 269,-1200.49 h60
M14 Component Bodies Bottom:
  text ".Layer_Name" at 269,-1200.49 h60
M15 Courtyards Top:
  text ".Layer_Name" at 269,-1200.49 h60
M16 Courtyards Bottom:
  text ".Layer_Name" at 269,-1200.49 h60
Drill Drawing:
  drawing of 158 lines, arcs and shapes, not listed
  text "Symbol" at -315.76,7243.02 h50.4
  text "Count" at 41.55,7243.02 h50.4
  text "Hole Size" at 456.44,7243.02 h50.4
  text "Plated" at 1263.21,7243.02 h50.4
  text "Hole Type" at 1620.52,7243.02 h50.4
  text "Drill Layer Pair" at 2137.38,7243.02 h50.4
  text "Pad Shape" at 2973.34,7243.02 h50.4
  text "Hole Length" at 3738.12,7243.02 h50.4
  text "30" at 41.55,7138.02 h42
  text "7.87mil (0.200mm)" at 456.44,7138.02 h42
  text "PTH" at 1263.21,7138.02 h42
  text "Round" at 1620.52,7138.02 h42
  text "TOP - BOTTOM" at 2137.38,7138.02 h42
  text "Rounded" at 2973.34,7138.02 h42
  text "-" at 3738.12,7138.02 h42
  text "4" at 41.55,7033.02 h42
  text "8.00mil (0.203mm)" at 456.44,7033.02 h42
  text "PTH" at 1263.21,7033.02 h42
  text "Round" at 1620.52,7033.02 h42
  text "TOP - BOTTOM" at 2137.38,7033.02 h42
  text "Rounded" at 2973.34,7033.02 h42
  text "-" at 3738.12,7033.02 h42
  text "7" at 41.55,6928.02 h42
  text "12.10mil (0.307mm)" at 456.44,6928.02 h42
  text "PTH" at 1263.21,6928.02 h42
  text "Round" at 1620.52,6928.02 h42
  text "TOP - BOTTOM" at 2137.38,6928.02 h42
  text "Rounded" at 2973.34,6928.02 h42
  text "-" at 3738.12,6928.02 h42
  text "B" at -336.81,6920.03 h46.67
  text "811" at 41.55,6823.02 h42
  text "12.20mil (0.310mm)" at 456.44,6823.02 h42
  text "PTH" at 1263.21,6823.02 h42
  text "Round" at 1620.52,6823.02 h42
  text "TOP - BOTTOM" at 2137.38,6823.02 h42
  text "Rounded" at 2973.34,6823.02 h42
  text "-" at 3738.12,6823.02 h42
  text "1" at 41.55,6718.02 h42
  text "17.72mil (0.450mm)" at 456.44,6718.02 h42
  text "PTH" at 1263.21,6718.02 h42
  text "Round" at 1620.52,6718.02 h42
  text "TOP - BOTTOM" at 2137.38,6718.02 h42
  text "Rounded" at 2973.34,6718.02 h42
  text "-" at 3738.12,6718.02 h42
  text "2" at 41.55,6613.02 h42
  text "23.62mil (0.600mm)" at 456.44,6613.02 h42
  text "PTH" at 1263.21,6613.02 h42
  text "Slot" at 1620.52,6613.02 h42
  text "TOP - BOTTOM" at 2137.38,6613.02 h42
  text "Rounded" at 2973.34,6613.02 h42
  text "51.18mil (1.300mm)" at 3738.12,6613.02 h42
  text "D" at -336.81,6605.03 h46.67
  text "3" at 41.55,6508.02 h42
  text "31.50mil (0.800mm)" at 456.44,6508.02 h42
  text "PTH" at 1263.21,6508.02 h42
  text "Rectangle" at 1620.52,6508.02 h42
  text "TOP - BOTTOM" at 2137.38,6508.02 h42
  text "Rounded Rectangle" at 2973.34,6508.02 h42
  text "78.74mil (2.000mm)" at 3738.12,6508.02 h42
  text "2" at 41.55,6403.02 h42
  text "31.50mil (0.800mm)" at 456.44,6403.02 h42
  text "PTH" at 1263.21,6403.02 h42
  text "Rectangle" at 1620.52,6403.02 h42
  text "TOP - BOTTOM" at 2137.38,6403.02 h42
  text "Rounded Rectangle" at 2973.34,6403.02 h42
  text "90.55mil (2.300mm)" at 3738.12,6403.02 h42
  text "2" at 41.55,6298.02 h42
  text "33.47mil (0.850mm)" at 456.44,6298.02 h42
  text "PTH" at 1263.21,6298.02 h42
  text "Round" at 1620.52,6298.02 h42
  text "TOP - BOTTOM" at 2137.38,6298.02 h42
  text "Rounded" at 2973.34,6298.02 h42
  text "-" at 3738.12,6298.02 h42
  text "4" at 41.55,6193.02 h42
  text "40.00mil (1.016mm)" at 456.44,6193.02 h42
  text "PTH" at 1263.21,6193.02 h42
  text "Round" at 1620.52,6193.02 h42
  text "TOP - BOTTOM" at 2137.38,6193.02 h42
  text "(Mixed)" at 2973.34,6193.02 h42
  text "-" at 3738.12,6193.02 h42
  text "2" at 41.55,6088.02 h42
  text "40.16mil (1.020mm)" at 456.44,6088.02 h42
  text "NPTH" at 1263.21,6088.02 h42
  text "Round" at 1620.52,6088.02 h42
  text "TOP - BOTTOM" at 2137.38,6088.02 h42
  text "Rounded" at 2973.34,6088.02 h42
  text "-" at 3738.12,6088.02 h42
  text "F" at -336.81,6080.03 h46.67
  text "3" at 41.55,5983.02 h42
  text "40.16mil (1.020mm)" at 456.44,5983.02 h42
  text "PTH" at 1263.21,5983.02 h42
  text "Round" at 1620.52,5983.02 h42
  text "TOP - BOTTOM" at 2137.38,5983.02 h42
  text "(Mixed)" at 2973.34,5983.02 h42
  text "-" at 3738.12,5983.02 h42
  text "E" at -336.81,5975.03 h46.67
  text "3" at 41.55,5878.02 h42
  text "47.24mil (1.200mm)" at 456.44,5878.02 h42
  text "PTH" at 1263.21,5878.02 h42
  text "Round" at 1620.52,5878.02 h42
  text "TOP - BOTTOM" at 2137.38,5878.02 h42
  text "(Mixed)" at 2973.34,5878.02 h42
  text "-" at 3738.12,5878.02 h42
  text "1" at 41.55,5773.02 h42
  text "70.87mil (1.800mm)" at 456.44,5773.02 h42
  text "NPTH" at 1263.21,5773.02 h42
  text "Rectangle" at 1620.52,5773.02 h42
  text "TOP - BOTTOM" at 2137.38,5773.02 h42
  text "Rounded Rectangle" at 2973.34,5773.02 h42
  text "71.00mil (1.803mm)" at 3738.12,5773.02 h42
  text "1" at 41.55,5668.02 h42
  text "157.48mil (4.000mm)" at 456.44,5668.02 h42
  text "PTH" at 1263.21,5668.02 h42
  text "Round" at 1620.52,5668.02 h42
  text "TOP - BOTTOM" at 2137.38,5668.02 h42
  text "Rounded" at 2973.34,5668.02 h42
  text "-" at 3738.12,5668.02 h42
  text "5" at 41.55,5563.02 h42
  text "160.00mil (4.064mm)" at 456.44,5563.02 h42
  text "NPTH" at 1263.21,5563.02 h42
  text "Round" at 1620.52,5563.02 h42
  text "TOP - BOTTOM" at 2137.38,5563.02 h42
  text "Rounded" at 2973.34,5563.02 h42
  text "-" at 3738.12,5563.02 h42
  text "881 Total" at 41.55,5458.02 h42
  text "Slot definitions :" at -315.76,5354.54 h42
  text "Routed Path Length" at 409.92,5354.54 h42
  text "= Calculated from tool start centre position to tool end centre position." at 1184.59,5354.54 h42
  text "Hole Length" at 409.92,5282.56 h42
  text "= Routed Path Length + Tool Size = Slot length as defined in the PCB layout" at 897.68,5282.56 h42
  text "Drill Table" at 69.28,5134.97 h50
  text "FOR PTH +/- 3MIL" at 65.74,5041.08 h50
  text "FOR NPTH +/- 2MIL" at 62.65,4964.49 h50
  text "FOR 7.874MIL DRILL +0/-7.874MIL" at 55.19,4883.32 h50
  text "FOR 8MIL DRILL +0/-8MIL" at 52.41,4793.95 h50
  text "FOR 12.1MIL DRILL +0/-12.1MIL" at 50.73,4709.43 h50
  text "FOR 12.2MIL DRILL +0/-12.2MIL" at 49.06,4631.01 h50
  text "Symbol" at 68.13,4296.78 h72
  text "Count" at 350.03,4296.78 h72
  text "Hole Size" at 642.44,4296.78 h72
  text "Plated" at 1160.39,4296.78 h72
  text "Hole Type" at 1407.86,4296.78 h72
  text "Drill Layer Pair" at 1768.15,4296.78 h72
  text "Hole Length" at 2260.97,4296.78 h72
  text "Routed Path Length" at 2673.27,4296.78 h72
  text "529" at 350.03,4172.6 h60
  text "5.90mil (0.150mm)" at 642.44,4172.6 h60
  text "PTH" at 1160.39,4172.6 h60
  text "Round" at 1407.86,4172.6 h60
  text "TOP - L2" at 1768.15,4172.6 h60
  text "-" at 2260.97,4172.6 h60
  text "-" at 2673.27,4172.6 h60
  text "529 Total" at 350.03,4048.42 h60
  text "FOR 5.9MIL DRILL +0/-5.9MIL" at 135.78,3879.38 h50
  text ".Layer_Name" at 269,-1200.49 h60
M17 Embedded Cavity:
  text ".Layer_Name" at 269,-1200.49 h60
M18 Embedded Assembly:
  text ".Layer_Name" at 269,-1200.49 h60
M19 Embedded Keepout:
  text ".Layer_Name" at 269,-1200.49 h60
2:
  drawing of 224 lines, arcs and shapes, not listed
